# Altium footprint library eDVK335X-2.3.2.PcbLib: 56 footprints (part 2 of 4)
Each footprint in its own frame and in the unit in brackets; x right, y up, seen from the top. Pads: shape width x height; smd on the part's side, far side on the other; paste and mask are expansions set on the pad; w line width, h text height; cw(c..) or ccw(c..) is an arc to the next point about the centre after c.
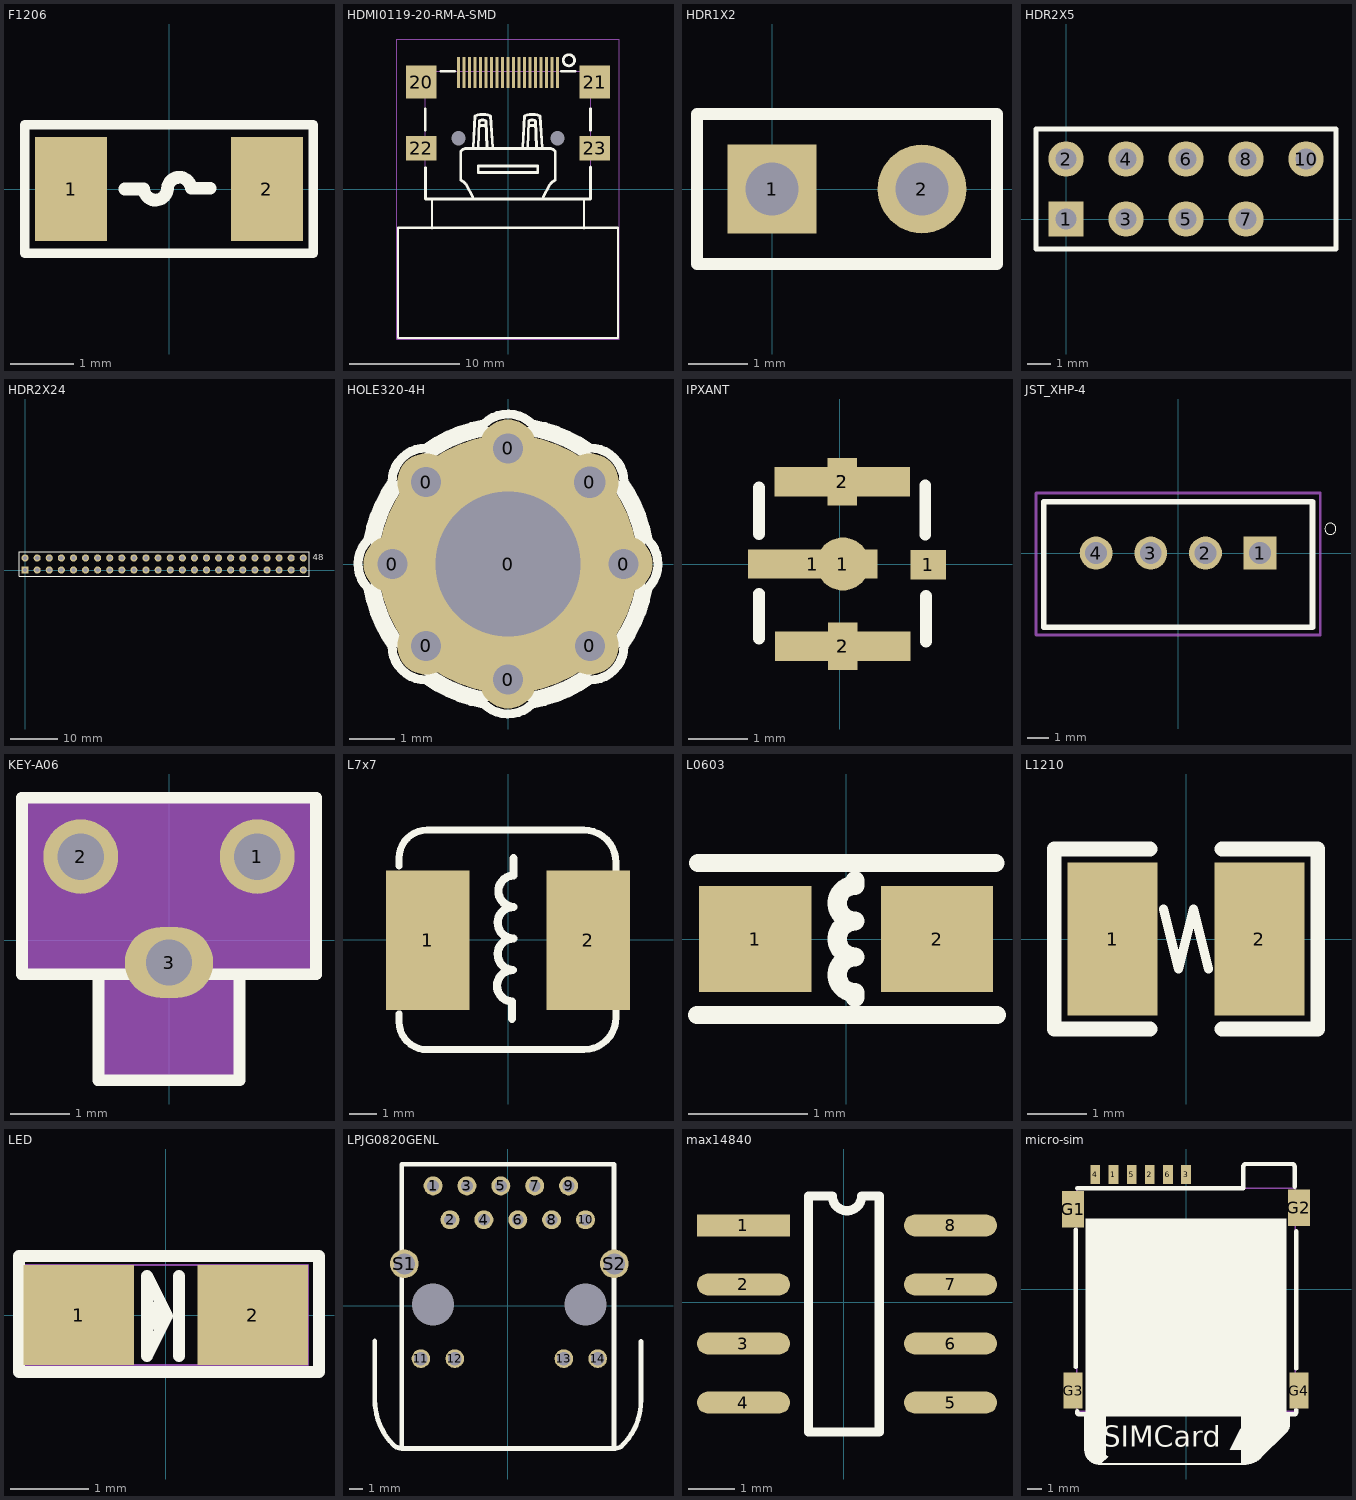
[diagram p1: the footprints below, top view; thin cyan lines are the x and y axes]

## F1206 [mil] "F1206"
pads (2):
  rect 45x65 smd: 1(-61,0) 2(61,0)
Top Overlay:
  lines w6: -90,-40 90,-40 90,40 -65,40 -90,40 -90,-40
  lines w7.87: -27.56,0 -15.75,0 ccw(c-8.37,0.49) -0.97,0.2 cw(c6.42,-0.1) 13.8,0.39 25.61,0.39
Mechanical 8:
  text "2" at 61,-4 h10
  text "1" at -61,-4 h10
Mechanical 10:
  lines w1: -90,-40 90,-40 90,40 -90,40 -90,-40

## HDMI0119-20-RM-A-SMD [mm] "HDMI0119-20-RM-A"
pads (25):
  rect 0.28x2.82 smd mask+0.08: 1(4.5,10.59) 2(4,10.59) 3(3.5,10.59) 4(3,10.59) 5(2.5,10.59) 6(2,10.59) 7(1.5,10.59) 8(1,10.59) 9(0.5,10.59) 10(0,10.59) 11(-0.5,10.59) 12(-1,10.59) 13(-1.5,10.59) 14(-2,10.59) 15(-2.5,10.59) 16(-3,10.59) 17(-3.5,10.59) 18(-4,10.59) 19(-4.5,10.59)
  rect 2.75x3 smd: 20(-7.875,9.699) 21(7.875,9.699)
  rect 2.75x2.2 smd: 22(-7.875,3.699) 23(7.875,3.699)
  round 0 hole 1.3 unplated: 24(4.5,4.599) 25(-4.5,4.599)
Top Overlay:
  circle w0.254: c5.531,11.694 r0.51
  lines w0.2: -6.9,-3.58 -6.9,-0.88 ; 6.91,-3.59 6.91,-0.89 ; -10,-13.526 10,-13.526 10,-3.526 -10,-3.526 -10,-13.526
  lines w0.25: -7.51,5.36 -7.51,7.3 ; -7.5,1.94 -7.5,-0.9 7.5,-0.9 7.5,2 ; -6.09,10.7 -4.83,10.7 ; 4.84,10.7 6.1,10.7 ; 7.49,5.34 7.49,7.28
  lines w0.254: -3.2,-0.71 -3.8,0.39 ccw(c-4.697,-0.219) -4.3,0.79 -4.3,3.39 cw(c-3.75,3.04) -3.8,3.69 3.8,3.69 cw(c3.75,3.04) 4.3,3.39 4.3,0.79 ccw(c4.65,-0.16) 3.8,0.39 3.2,-0.71 ; -3.163,3.739 -2.992,6.642 cw(c-2.297,4.873) -1.603,6.642 -1.383,3.739 ; -2.71,3.774 -2.61,6.174 cw(c-2.31,5.773) -2.01,6.174 -1.91,3.774 ; -2.61,5.774 -2.01,5.774 ; 1.337,3.739 1.508,6.642 cw(c2.203,4.873) 2.898,6.642 3.117,3.739 ; 1.79,3.774 1.89,6.174 cw(c2.19,5.773) 2.49,6.174 2.59,3.774 ; 1.89,5.774 2.49,5.774 ; -2.7,1.49 -2.7,2.09 2.7,2.09 2.7,1.49 -2.7,1.49
  text "19" at -6.168,11.206 h0
Mechanical 7:
  lines w0.025: -10.1,-13.626 10.1,-13.626 10.1,13.626 -10.1,13.626 -10.1,-13.626
Mechanical 14:
  text "16" at -3.508,10.59 h0.64
  text "15" at -3.008,10.59 h0.64
  text "18" at -4.508,10.59 h0.64
  text "19" at -5.008,10.59 h0.64
  text "12" at -1.508,10.59 h0.64
  text "10" at -0.508,10.59 h0.64
  text "6" at 1.746,10.59 h0.64
  text "1" at 4.246,10.59 h0.64
  text "3" at 3.246,10.59 h0.64
  text "4" at 2.746,10.59 h0.64
  text "9" at 0.246,10.59 h0.64
  text "7" at 1.246,10.59 h0.64
  text "22" at -7.758,3.69 h0.64
  text "20" at -7.758,9.69 h0.64
  text "23" at 6.742,3.69 h0.64
  text "11" at -1.008,10.59 h0.64
  text "17" at -4.008,10.59 h0.64
  text "5" at 2.246,10.59 h0.64
  text "2" at 3.746,10.59 h0.64
  text "8" at 0.746,10.59 h0.64
  text "21" at 6.742,9.69 h0.64
  text "14" at -2.508,10.59 h0.64
  text "13" at -2.008,10.59 h0.64
  text "25" at 1.992,8.04 h0.64
  text "24" at -3.008,8.04 h0.64
Mechanical 15:
  lines w0.1: -7.5,-0.91 7.5,-0.91 7.5,10.69 -7.5,10.69 -7.5,-0.91

## HDR1X2 [mm] "Connector; Header; 2 Position"
pads (2):
  rect 1.5x1.5 hole 0.9: 1(0,0)
  round 1.5 hole 0.9: 2(2.54,0)
Top Overlay:
  lines w0.2: -1.27,-1.27 3.81,-1.27 3.81,1.27 -1.27,1.27 -1.27,-1.27

## HDR2X5 [mm] "Connector; Header; 5x2 Position"
pads (9):
  rect 1.5x1.5 hole 0.9: 1(0,0)
  round 1.5 hole 0.9: 2(0,2.54) 3(2.54,0) 4(2.54,2.54) 5(5.08,0) 6(5.08,2.54) 7(7.62,0) 8(7.62,2.54) 10(10.16,2.54)
Top Overlay:
  lines w0.2: -1.27,-1.27 -1.27,3.81 11.43,3.81 11.43,-1.27 -1.27,-1.27

## HDR2X24 [mm] "Connector; Header; 24x2 Position"
pads (48):
  rect 1.5x1.5 hole 0.9: 1(0,0)
  round 1.5 hole 0.9: 2(0,2.54) 3(2.54,0) 4(2.54,2.54) 5(5.08,0) 6(5.08,2.54) 7(7.62,0) 8(7.62,2.54) 9(10.16,0) 10(10.16,2.54) 11(12.7,0) 12(12.7,2.54) 13(15.24,0) 14(15.24,2.54) 15(17.78,0) 16(17.78,2.54) 17(20.32,0) 18(20.32,2.54) 19(22.86,0) 20(22.86,2.54) 21(25.4,0) 22(25.4,2.54) 23(27.94,0) 24(27.94,2.54) 25(30.48,0) 26(30.48,2.54) 27(33.02,0) 28(33.02,2.54) 29(35.56,0) 30(35.56,2.54) 31(38.1,0) 32(38.1,2.54) 33(40.64,0) 34(40.64,2.54) 35(43.18,0) 36(43.18,2.54) 37(45.72,0) 38(45.72,2.54) 39(48.26,0) 40(48.26,2.54) 41(50.8,0) 42(50.8,2.54) 43(53.34,0) 44(53.34,2.54) 45(55.88,0) 46(55.88,2.54) 47(58.42,0) 48(58.42,2.54)
Top Overlay:
  lines w0.2: -1.27,-1.27 -1.27,3.81 59.69,3.81 59.69,-1.27 -1.27,-1.27
  text "48" at 60.452,2.032 h1.27

## HOLE320-4H [mm] "HOLE320-4H"
pads (9):
  round 1.27 / inner round 1.524 / far side round 1.27 hole 0.66: 0(-2.546,0) 0(-1.8,-1.8) 0(-1.8,1.8) 0(0,-2.546) 0(0,2.546) 0(1.8,-1.8) 0(2.546,0)
  round 5.7 hole 3.2: 0(0,0)
  round 1.27 hole 0.7: 0(1.8,1.8)
Top Overlay:
  circle w0.2: c0,0 r2.952
  lines w0.2: -3.079,0.545 cw(c0,0) -2.556,1.801 ; -3.069,0.543 ccw(c-2.546,0) -3.081,-0.531 ccw(c0,0) -2.556,-1.801 ; -2.554,-1.8 ccw(c-1.8,-1.8) -1.8,-2.554 ; -2.554,1.8 cw(c-1.8,1.8) -1.8,2.554 ; -1.801,-2.556 ccw(c0,0) -0.545,-3.079 ; -1.801,2.556 cw(c0,0) -0.531,3.081 cw(c0,2.546) 0.543,3.069 ; -0.543,-3.069 ccw(c0,-2.546) 0.531,-3.081 ccw(c0,0) 1.801,-2.556 ; 0.545,3.079 cw(c0,0) 1.801,2.556 ; 1.8,-2.554 ccw(c1.8,-1.8) 2.554,-1.8 ; 1.8,2.554 cw(c1.8,1.8) 2.554,1.8 ; 2.556,-1.801 ccw(c0,0) 3.079,-0.545 ; 2.556,1.801 cw(c0,0) 3.081,0.531 cw(c2.546,0) 3.069,-0.543
Mechanical 8:
  text "1" at -1.108,-0.3 h0.64
  text "5" at 1.292,-1.9 h0.64
  text "3" at 1.292,1.2 h0.64
  text "4" at -1.908,-1.9 h0.64
  text "2" at -2.008,1.3 h0.64

## IPXANT [mm]
height 15.51
pads (7):
  rect 2.2x0.5 smd: 1(-0.457,0)
  round 0.9 smd: 1(0.052,0)
  rect 0.6x0.5 smd: 1(1.499,-0.013)
  rect 0.5x0.8 smd: 2(0.038,1.397) 2(0.051,-1.397)
  rect 2.3x0.5 smd: 2(0.038,1.397) 2(0.051,-1.397)
Top Overlay:
  lines w0.2: -1.372,-1.267 -1.372,-0.505 ; -1.372,0.511 -1.372,1.298 ; 1.448,0.498 1.448,1.336 ; 1.46,-1.318 1.46,-0.543

## JST_XHP-4 [mm]
pads (4):
  rect 1.508x1.508 hole 1: 1(3.75,0)
  round 1.508 hole 1: 2(1.25,0) 3(-1.25,0) 4(-3.75,0)
Top Overlay:
  circle w0: c6.97,1.11 r0.254
  lines w0.254: -6.15,-3.4 -6.15,2.35 6.15,2.35 6.15,-3.4 -6.15,-3.4
Mechanical 16:
  lines w0.127: -6.5,-3.75 -6.5,2.75 6.5,2.75 6.5,-3.75 -6.5,-3.75

## KEY-A06 [mil] "KEY-A06"
pads (3):
  round 50 hole 31: 1(59.05,55.87) 2(-59.06,55.87)
  oval 59.06x47.24 hole 31: 3(0,-15)
Top Overlay:
  circle w3.94: c-47.25,-93.74 r1.97
  circle w3.94: c-47.25,-22.87 r1.97
  circle w3.94: c47.24,-93.74 r1.97
  circle w3.94: c47.24,-22.87 r1.97
  circle w3.94: c-98.43,95.24 r1.97
  circle w3.94: c98.42,95.24 r1.97
  circle w3.94: c98.42,-22.87 r1.97
  circle w3.94: c98.42,95.24 r1.97
  circle w3.94: c-98.43,-22.87 r1.97
  circle w3.94: c-98.43,95.24 r1.97
  circle w3.94: c-98.43,-22.87 r1.97
  circle w3.94: c98.42,-22.87 r1.97
  circle w3.94: c-47.25,-93.74 r1.97
  circle w3.94: c47.24,-93.74 r1.97
  circle w1: c0,-15 r13.81
  circle w1: c0,-15 r13.81
  circle w1: c0,-15 r11.81
  circle w1: c-59.06,55.87 r13.81
  circle w1: c-59.06,55.87 r13.81
  circle w1: c-59.06,55.87 r11.81
  circle w1: c59.05,55.87 r13.82
  circle w1: c59.05,55.87 r13.82
  circle w1: c59.05,55.87 r11.82
  lines w7.87: -47.25,-22.87 -47.25,-93.74 47.24,-93.74 47.24,-22.87 ; -98.43,-22.87 -98.43,95.24 98.42,95.24 98.42,-22.87 -98.43,-22.87
Mechanical 8:
  text "3" at 0,-5 h25
  text "2" at -59.06,65.87 h25
  text "1" at 59.05,65.87 h25
Mechanical 9:
  region: -100,95 -100,-25 -45,-25 -45,-95 45,-95 45,-25 100,-25 100,95

## L7x7 [mil] "L7X7"
pads (2):
  rect 120x200 smd: 1(-115.2,-0.34) 2(115.2,-0.34)
Top Overlay:
  circle w5: c-156.21,-106.19 r2.5
  circle w5: c-156.21,-117.48 r2.5
  circle w5: c-156.22,-117.48 r2.5
  circle w5: c154.97,111.25 r2.5
  circle w5: c154.97,111.25 r2.5
  circle w5: c154.97,100 r2.5
  circle w5: c108.74,157.47 r2.5
  circle w5: c108.74,157.47 r2.5
  circle w5: c-156.21,117.47 r2.5
  circle w5: c-156.21,117.47 r2.5
  circle w5: c-156.21,106.17 r2.5
  lines w10: -156.21,-106.19 -156.21,-117.48 ccw(c-116.22,-117.48) -116.22,-157.49 108.74,-157.49 ccw(c108.75,-111.27) 154.97,-111.27 154.97,-100 ; -156.21,106.17 -156.21,117.47 cw(c-116.21,117.47) -116.21,157.47 108.74,157.47 cw(c108.74,111.25) 154.97,111.25 154.97,100
  lines w11.81: 5.91,-113.13 5.91,-88.5 cw(c6.89,-65.88) 6.89,-43.24 cw(c7.88,-20.63) 7.88,2.01 ; 6.89,2.01 cw(c7.87,24.63) 7.87,47.27 cw(c8.86,69.88) 7.87,92.5 7.87,117.13
Mechanical 8:
  text "1" at -115.2,13.65 h35
  text "2" at 115.2,13.65 h35

## L0603 [mil] "L0603"
pads (2):
  rect 37x35 smd: 1(-30,0) 2(30,0)
Top Overlay:
  lines w6: -49.21,-25.08 49.76,-25.08 ; -48.78,25.08 49.21,25.08
  lines w6.3: 2.95,-19.29 2.95,-17.72 cw(c2.95,-11.81) 2.95,-5.91 cw(c2.95,0) 2.95,5.91 cw(c2.95,11.81) 2.95,17.72 2.95,19.29
Mechanical 8:
  text "1" at -30,-10 h25
  text "2" at 30,-10 h25

## L1210 [mil]
pads (2):
  rect 60x102.36 smd mask+2: 1(-49,0) 2(49,0)
Top Overlay:
  lines w6: -15,20 -5,-20 5,20 15,-20
  lines w10: -24,-60 -88,-60 -88,60 -24,60 ; 24,-60 88,-60 88,60 24,60

## LED [mm] "LED"
pads (2):
  rect 1.4x1.27 smd: 1(-1.105,0) 2(1.105,0)
Top Overlay:
  region: -0.237,-0.262 0.017,-0.008 -0.237,0.246
  lines w0.152: 0.167,-0.516 0.167,0.5 ; -1.865,-0.725 1.945,-0.725 1.945,0.754 -1.865,0.754 -1.865,-0.725 ; -0.237,-0.516 0.017,-0.008 -0.237,0.5 -0.237,-0.516
Mechanical 8:
  text "2" at 1.105,-0.254 h0.64
  text "1" at -1.105,-0.254 h0.64
Mechanical 10:
  lines w0.025: -1.805,-0.635 -1.805,0.635 1.805,0.635 1.805,-0.635 -1.805,-0.635

## LPJG0820GENL [mil] "LPJG0820GENL"
pads (18):
  round 56 / inner round 60 / far side round 56 hole 35: 1(-221,354.5) 2(-171,254.5) 3(-121,354.5) 4(-71,254.5) 5(-21,354.5) 6(29,254.5) 7(79,354.5) 8(129,254.5) 9(179,354.5) 10(229,254.5)
  round 55 / inner round 60 / far side round 55 hole 40: 11(-257,-155.5) 12(-157,-155.5) 13(165,-155.5) 14(265,-155.5)
  round 0 hole 125 unplated: " "(-221,4.5) " "(229,4.5)
  round 85 / inner round 60 / far side round 85 hole 62: S1(-306,124.5) S2(314,124.5)
Top Overlay:
  lines w13.78: -393,-103.5 -393,-277.72 ccw(c-205.22,-277.72) -338,-410.5 ccw(c-316.27,-388.77) -316.27,-419.5 -313,-419.5 ; 393,-104.5 393,-278.72 cw(c205.22,-278.72) 338,-411.5 cw(c316.27,-389.77) 316.27,-420.5 313,-420.5 ; 313,-420.5 313,418.5 -313,418.5 -313,-420.5 313,-420.5
Mechanical 8:
  text "9" at 169,354.5 h25
  text "S2" at 294,124.5 h25
  text "10" at 209,254.5 h25
  text "7" at 69,354.5 h25
  text "5" at -31,354.5 h25
  text "6" at 19,254.5 h25
  text "8" at 119,254.5 h25
  text "14" at 245,-155.5 h25
  text "13" at 145,-155.5 h25
  text "3" at -131,354.5 h25
  text "4" at -81,254.5 h25
  text "12" at -177,-155.5 h25
  text "1" at -231,354.5 h25
  text "2" at -181,254.5 h25
  text "11" at -277,-155.5 h25
  text "S1" at -326,124.5 h25
Mechanical 10:
  lines w3.94: -392.34,-105.54 -392.34,-276.9 ccw(c-203.4,-276.9) -337,-410.5 ccw(c-315.27,-388.77) -315.27,-419.5 -311.99,-419.5 ; 393.34,-105.54 393.34,-276.9 cw(c204.4,-276.9) 338,-410.5 cw(c316.27,-388.77) 316.27,-419.5 312.98,-419.5 ; 312.98,-419.5 312.98,419.08 -313,419.08 -313,-419.5 312.98,-419.5

## max14840 [mm]
pads (8):
  rect 2x0.47 smd: 1(-2.159,1.651)
  oval 2x0.47 smd: 2(-2.159,0.381) 3(-2.159,-0.889) 4(-2.159,-2.159) 5(2.295,-2.159) 6(2.295,-0.889) 7(2.295,0.381) 8(2.295,1.651)
Top Overlay:
  lines w0.2: -0.762,-2.794 0.762,-2.794 0.762,2.286 0.386,2.286 cw(c0.068,2.286) -0.25,2.286 -0.762,2.286 -0.762,-2.794

## micro-sim [mm]
pads (10):
  rect 0.686x1.346 smd: 1(-5.07,8.015) 2(-2.53,8.015) 3(0.01,8.015) 4(-6.34,8.015) 5(-3.8,8.015) 6(-1.26,8.015)
  rect 1.524x2.54 smd: G1(-7.9,5.59) G2(7.9,5.68)
  rect 1.3x2.54 smd: G3(-7.9,-7.09) G4(7.9,-7.09)
Top Overlay:
  rectangle: -7.025,-8.775 7.025,4.95
  region: -7.05,-8.75 -7.05,-11.25 -7,-11.3 -7,-11.575 -6.775,-11.8 -6.775,-11.95 -6.625,-11.95 -6.35,-12.225 -5.95,-12.225 -5.45,-11.725 -5.6,-11.575 -5.6,-8.775 -7.025,-8.775
  region: 3.875,-8.75 3.875,-12.2 4.575,-12.2 4.8,-11.975 4.975,-11.975 7.2,-9.75 7.2,-8.75
  lines w0.16: -7.05,-8.75 -7.05,-11.25 ccw(c-6.013,-11.188) -5.95,-12.225 4.175,-12.225 ccw(c4.061,-10.633) 5.188,-11.763 6.925,-10.025 ccw(c6.388,-9.412) 7.2,-9.35 ; 7.2,-9.4 7.2,-8.75
  lines w0.3: -7.7,-5.45 -7.7,4.15 ; -7.6,-8.55 -7.6,-8.65 ccw(c-7.5,-8.65) -7.5,-8.75 7.6,-8.75 ccw(c7.6,-8.65) 7.7,-8.65 7.7,-8.45 ; -7.6,7.05 4,7.05 4,8.55 cw(c4.2,8.55) 4.2,8.75 7.4,8.75 cw(c7.4,8.55) 7.6,8.55 7.6,7.15 ; 7.7,-5.55 7.7,4.05
  text "SIMCard ▲" at -5.825,-11.5 h2.5
Mechanical 8:
  text "2" at -2.3,7.95 h0.64
  text "4" at -6.1,7.85 h0.64
  text "1" at -4.8,7.85 h0.64
  text "5" at -3.5,7.85 h0.64
  text "6" at -1,7.95 h0.64
  text "3" at 0.3,7.75 h0.64
  text "G2" at 9.316,5.25 h0.64
  text "G3" at -6.684,-7.35 h0.64
  text "G4" at 9.216,-7.55 h0.64
Mechanical 10:
  lines w0.1: 4,7.05 4,8.75 7.65,8.75 7.65,7.05 ; 7.65,7.05 -7.65,7.05 -7.65,-8.55 7.65,-8.55 7.65,7.05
